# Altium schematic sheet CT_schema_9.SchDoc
size 277 x 170 mm
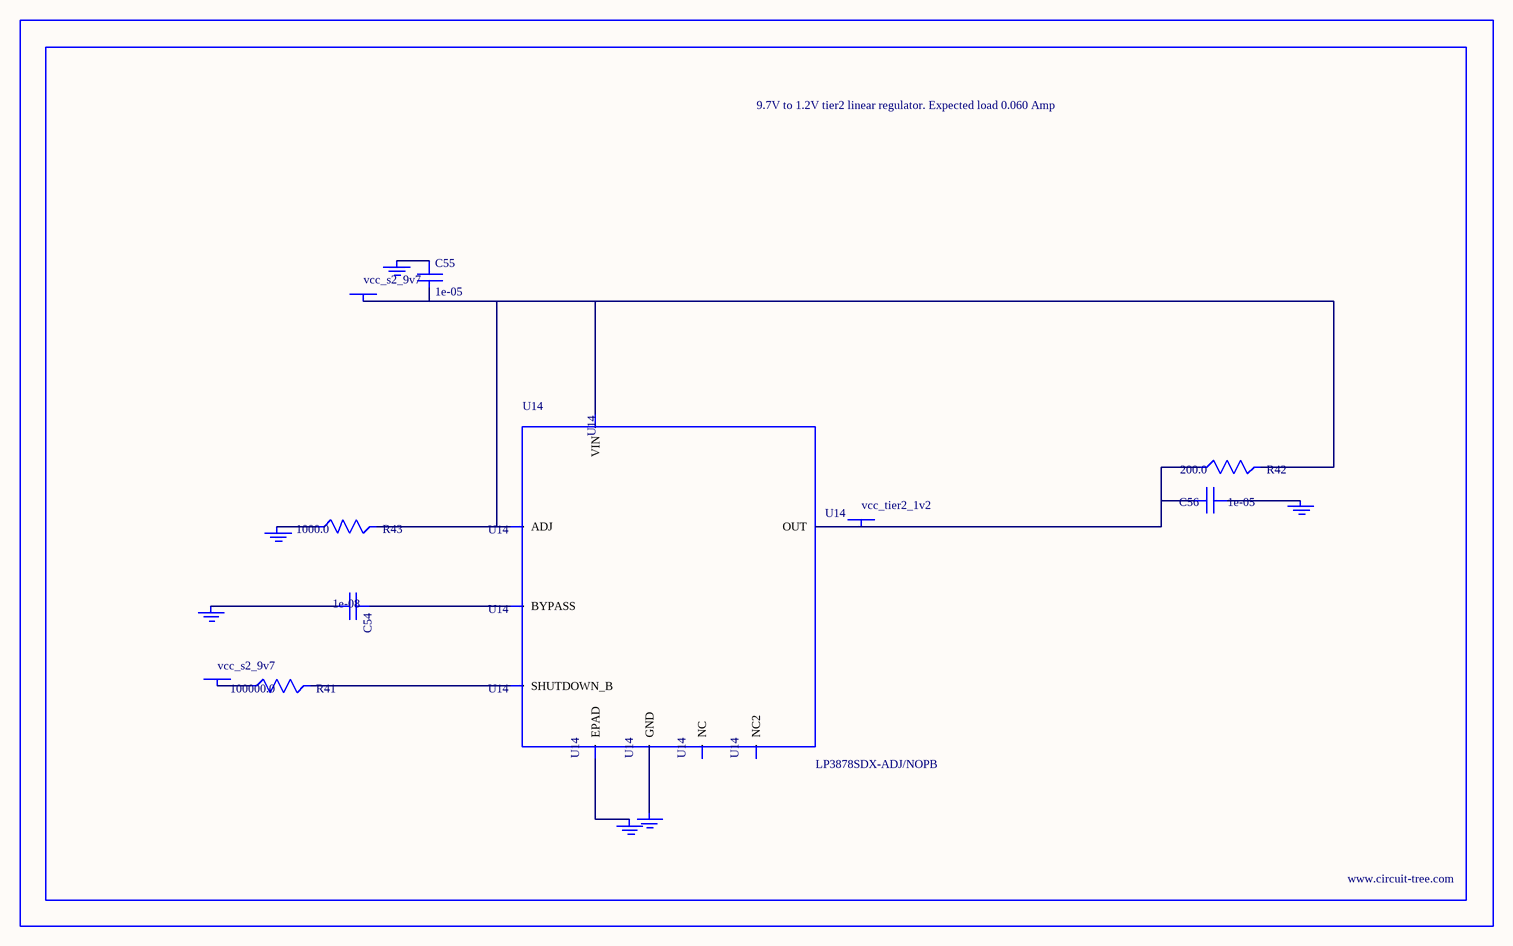
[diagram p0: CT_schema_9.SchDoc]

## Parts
BORDER8  (no value)
C54  1e-08  [C0402]
C55  1e-05  [C1206]
C56  1e-05  [C0805]
GND_INSTANCE_8_0  (no value)
GND_INSTANCE_8_1  (no value)
GND_INSTANCE_8_2  (no value)
GND_INSTANCE_8_3  (no value)
GND_INSTANCE_8_4  (no value)
GND_INSTANCE_8_5  (no value)
POWER_INSTANCE_8_0  vcc_s2_9v7
POWER_INSTANCE_8_1  vcc_s2_9v7
POWER_INSTANCE_8_2  vcc_tier2_1v2
R41  100000.0  [R0603]
R42  200.0  [R0603]
R43  1000.0  [R0603]
U14  LP3878SDX-ADJ/NOPB  [WSON-8]

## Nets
NetC54_1: C54.1 U14.1(BYPASS)
NetC54_2: C54.2 GND_INSTANCE_8_0.0(GND)
NetC55_1: C55.1 GND_INSTANCE_8_1.0(GND)
NetC55_2: C55.2 POWER_INSTANCE_8_0.0(PWR) R42.2 R43.2 U14.4(VIN) U14.6(ADJ)
NetC56_1: C56.1 GND_INSTANCE_8_2.0(GND)
NetC56_2: C56.2 POWER_INSTANCE_8_2.0(PWR) R42.1 U14.5(OUT)
NetGND_INSTANCE_8_3_0: GND_INSTANCE_8_3.0(GND) R43.1
NetGND_INSTANCE_8_4_0: GND_INSTANCE_8_4.0(GND) U14.PAD(EPAD)
NetGND_INSTANCE_8_5_0: GND_INSTANCE_8_5.0(GND) U14.3(GND)
NetPOWER_INSTANCE_8_1_0: POWER_INSTANCE_8_1.0(PWR) R41.1
NetR41_2: R41.2 U14.8(SHUTDOWN_B)

Not connected (* = marked no-connect by the designer): U14 2(NC) 7(NC2)

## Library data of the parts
BORDER8 = BORDER_PAGE8
C54 = C0402C103K3RAC
C55 = C1206C106K3RACTU
C56 = GRM219R60J106ME19D
GND_INSTANCE_8_0-GND_INSTANCE_8_5 = GND
POWER_INSTANCE_8_0-POWER_INSTANCE_8_2 = PWR
R41 = RC0603JR-07100KL
R42 = RC0603JR-07200RL
R43 = RC0603JR-071KL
